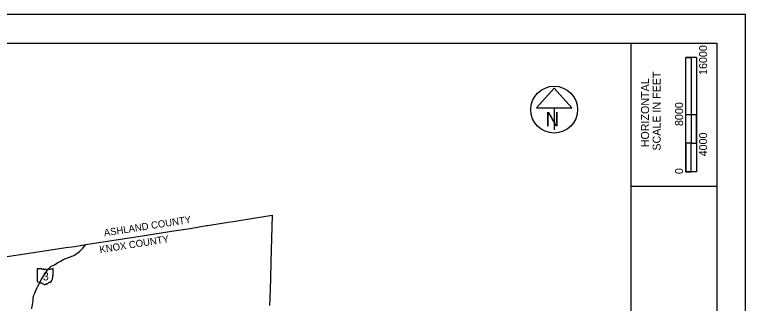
# Model space of a CAD drawing. Extents: x 1851937 to 2123937, y 789467 to 965467.
# Drawn here: x 2021685 to 2123937, y 925060 to 965467 of the extents above; entities that cross this region are included whole.
import ezdxf

# ---------------------------------------------------------------- set-up
doc = ezdxf.new("R2010")
doc.units = 0
for name, color, linetype in [('GM_X_County', 7, 'Continuous'), ('GM_X_County_Text', 7, 'Continuous'), ('GM_X_State_Location', 7, 'Continuous'), ('GM_X_State_Route', 7, 'Continuous'), ('GM_X_State_Shield', 7, 'Continuous'), ('SH_Border', 7, 'Continuous'), ('SH_Cut_Line', 7, 'Continuous'), ('SH_Data', 7, 'Continuous'), ('SH_Masking', 7, 'Continuous'), ('SH_Text', 7, 'Continuous')]:
    doc.layers.add(name, color=color, linetype=linetype)

msp = doc.modelspace()

# ---------------------------------------------------------------- linework, layer by layer
at = {"layer": 'GM_X_County'}
msp.add_lwpolyline([(2017735, 931206), (2023098, 932000), (2028854, 932870), (2030107, 933016), (2031110, 933200), (2031649, 933280), (2034948, 933801), (2038384, 934331), (2043974, 935218), (2046245, 935559), (2048555, 935947), (2048693, 935977), (2051562, 936437), (2052245, 936538), (2055094, 937003), (2057724, 937391), (2057545, 930886), (2057485, 928488), (2057387, 925735), (2057341, 924765)], dxfattribs=at)
at = {"layer": 'GM_X_State_Route'}
for points in [[(2025077, 927735), (2025396, 928353), (2025530, 928568), (2025748, 928871), (2025934, 929145), (2026298, 929697), (2026469, 929952), (2026598, 930102), (2026670, 930162), (2026722, 930196), (2026799, 930249), (2027258, 930471), (2027751, 930766), (2028129, 930979), (2028379, 931133), (2028520, 931213), (2028651, 931276), (2028820, 931342), (2029076, 931428), (2029349, 931512), (2029713, 931654), (2029887, 931721), (2030084, 931814), (2030238, 931927), (2030572, 932159), (2030742, 932312), (2030911, 932447), (2031049, 932589)], [(2031049, 932589), (2031119, 932678), (2031169, 932728), (2031225, 932786), (2031651, 933278)], [(2024506, 926484), (2024563, 926610), (2024693, 926970), (2024828, 927266), (2024877, 927367), (2025072, 927726), (2025077, 927735)], [(2024266, 925358), (2024275, 925520), (2024285, 925772), (2024294, 925888), (2024312, 925997), (2024339, 926107), (2024420, 926296), (2024506, 926484)], [(2024079, 924295), (2024091, 924454), (2024120, 924627), (2024142, 924729), (2024166, 924813), (2024178, 924861), (2024195, 924962), (2024225, 925154), (2024237, 925195), (2024266, 925358)]]:
    msp.add_lwpolyline(points, dxfattribs=at)
at = {"layer": 'GM_X_State_Shield'}
for p, q in [((2024820, 929859), (2024820, 928158)), ((2025499, 929888), (2024842, 929888)), ((2027062, 929040), (2027062, 929930)), ((2027062, 929041), (2027062, 929040))]:
    msp.add_line(p, q, dxfattribs=at)
for centre, radius, start, end in [((2024846, 929862), 26, 98.1301, 188.1301), ((2025655, 930086), 252, 231.61951, 271.11188), ((2025739, 928933), 904, 80.48669, 94.98827), ((2025944, 929871), 72.7, 219.79206, 297.10237), ((2026051, 929675), 151, 54.46668, 119.14113), ((2026246, 929944), 182, 233.85621, 294.82819), ((2026567, 929369), 478, 97.34618, 120.76885), ((2026263, 932207), 2377, 275.84447, 288.90645), ((2027037, 929934), 25, 351.86209, 97.738), ((2026397, 928555), 595, 292.30889, 8.98584), ((2027151, 928668), 169, 136.8065, 186.92959), ((2027056, 928975), 38.6, 107.94398, 210.33697), ((2026810, 928863), 232, 340.03296, 23.64957), ((2027035, 929037), 26.7, 289.60381, 7.73413), ((2024846, 928154), 26.2, 171.95839, 258.30661), ((2024850, 928328), 200, 267.33899, 280.60386), ((2024891, 928060), 72.1, 29.74838, 93.27175), ((2025801, 929588), 1716, 240.41292, 257.1985), ((2025290, 927393), 537, 47.18416, 75.83597), ((2025870, 928051), 341, 230.70037, 286.29184), ((2026067, 927463), 280, 85.69512, 111.20995), ((2026092, 927924), 182, 268.77702, 315.54927), ((2026256, 927759), 51.1, 65.75173, 132.64842), ((2026235, 927993), 192, 282.87319, 323.27711), ((2026647, 927680), 326, 94.40312, 142.57675)]:
    msp.add_arc(centre, radius, start, end, dxfattribs=at)
at = {"layer": 'SH_Border'}
for p, q in [((2107937, 793467), (2107937, 961467)), ((2107937, 941467), (2119937, 941467))]:
    msp.add_line(p, q, dxfattribs=at)
msp.add_lwpolyline([(1863937, 961467), (2119937, 961467), (2119937, 793467), (1863937, 793467)], close=True, dxfattribs=at)
at = {"layer": 'SH_Cut_Line'}
msp.add_lwpolyline([(1851937, 789467), (2123937, 789467), (2123937, 965467), (1851937, 965467)], close=True, dxfattribs=at)
at = {"layer": 'SH_Data'}
for p, q in [((2115591, 943467), (2115591, 959467)), ((2117091, 959467), (2115591, 959467)), ((2115591, 951467), (2115591, 959467)), ((2115591, 959467), (2116337, 959467)), ((2116337, 959467), (2116344, 959467)), ((2116344, 959467), (2116344, 951467)), ((2117091, 959467), (2117091, 943467)), ((2116344, 951467), (2115591, 951467)), ((2117084, 951467), (2116337, 951467)), ((2116337, 951467), (2116337, 947467)), ((2117084, 947467), (2117084, 951467)), ((2116337, 947467), (2115591, 947467)), ((2115591, 947467), (2115591, 943467)), ((2116337, 943467), (2116337, 947467)), ((2116337, 947467), (2117084, 947467)), ((2117091, 943467), (2115591, 943467)), ((2115591, 943467), (2116337, 943467))]:
    msp.add_line(p, q, dxfattribs=at)
at = {"layer": 'SH_Masking'}
msp.add_circle((2097177, 952176), 3280, dxfattribs=at)
at = {"layer": 'SH_Text'}
for p, q in [((2097176, 955166), (2094716, 952436)), ((2099637, 952436), (2097176, 955166)), ((2094716, 952436), (2099637, 952436)), ((2097176, 952436), (2097176, 949342))]:
    msp.add_line(p, q, dxfattribs=at)
msp.add_circle((2097177, 952176), 3280, dxfattribs=at)

# ---------------------------------------------------------------- texts
at = {"layer": 'GM_X_County_Text'}
for s, rotation, p in [('ASHLAND COUNTY', 8.93999, (2034250, 934426)), ('KNOX COUNTY', 8.99869, (2033643, 932083))]:
    msp.add_text(s, height=1000, rotation=rotation, dxfattribs=at).set_placement(p)
at = {"layer": 'GM_X_State_Location'}
msp.add_text('3', height=1, rotation=0.00001, dxfattribs=at).set_placement((2025919, 929157))
for s in ['s', 'r']:
    msp.add_text(s, height=1, dxfattribs=at).set_placement((2026070, 929230))
at = {"layer": 'GM_X_State_Shield'}
msp.add_text('3', height=1121, dxfattribs=at).set_placement((2025634, 928278))
at = {"layer": 'SH_Data'}
for s, p in [('16000', (2118580, 957026)), ('SCALE IN FEET', (2112077, 946432)), ('HORIZONTAL', (2110457, 946901)), ('8000', (2115221, 949873)), ('4000', (2118580, 945635)), ('0', (2115221, 943157))]:
    msp.add_text(s, height=1120, rotation=90, dxfattribs=at).set_placement(p)
at = {"layer": 'SH_Text'}
msp.add_text('N', height=2000, dxfattribs=at).set_placement((2095966, 949845))

doc.saveas('drawing.dxf')
